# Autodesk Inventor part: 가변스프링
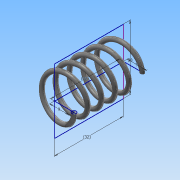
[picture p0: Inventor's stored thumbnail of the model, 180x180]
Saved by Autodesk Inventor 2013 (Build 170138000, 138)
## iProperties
Created: 2017-12
Part Number: 가변스프링
Material: 스테인리스강
Document SubType Name: Modeling
Designer: Administrator
Density: 8.08 g/cm^3
Mass: 7.08194 g
Surface Area: 17.761 cm^2
Volume: 0.876478 cm^3
Author: Administrator
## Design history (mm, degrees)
sketch "스케치1"
  geometry: L1 (0, 0)-(9, 0); L2 (0, 0)-(0, 32); L3 (0, 32)-(9, 32); C1 r 1 at (9, 0)
  constraints: 6 end point, 2 perpendicular, 1 centre point, 1 coincident, 1 horizontal
  dimensions: "d1" = 9 distance of L1.start L1.end; "d2" = 2 diameter of C1; "d3" = 32 distance of L1.start L2.end (derived); "d4" = 9 distance of L2.end L3.end
feature "코일1" sketch "스케치1" pitch "d5" = 10; turns "d7" = 5; dims "d6" = 32 (= d3), "d8" = 0, angle "d9" = 90 deg, angle "d10" = 90 deg, "d11" = 0, "d12" = 0
sketch "스케치2"
  geometry: L1 (32, 15)-(0, 15); L2 (0, 15)-(0, -15); L3 (0, -15)-(32, -15); L4 (32, -15)-(32, 15); 2 further points
  constraints: 8 end point, 2 parallel, 1 coincident, 1 horizontal, 1 midpoint, 1 perpendicular
  dimensions: "d13" = 32 distance of L2.end L3.end (derived); "d15" = 30 distance of L3.end L1.start
extrude "돌출1" sketch "스케치2" stored distance "d16" = 0; taper "d17" = 0 deg
node "솔리드1"
